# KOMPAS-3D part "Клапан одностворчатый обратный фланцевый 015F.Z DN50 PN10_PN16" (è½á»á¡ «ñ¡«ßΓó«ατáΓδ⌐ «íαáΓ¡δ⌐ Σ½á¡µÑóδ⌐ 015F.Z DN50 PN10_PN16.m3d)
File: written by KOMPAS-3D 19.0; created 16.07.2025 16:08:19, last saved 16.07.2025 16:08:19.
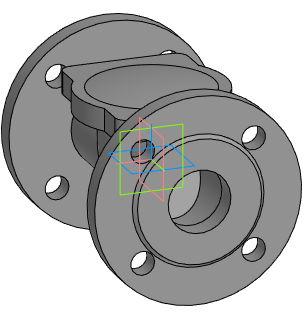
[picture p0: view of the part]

Document properties: Полное имя файла: E:\Dendor Работа Сачек\3D для проектировщиков\5.4 Тип 015F.Z. Клапан одностворчатый обратный фланцевый\stp_Клапан одностворчатый обратный фланцевый 015F.Z PN10_16\Клапан одностворчатый обратный фланцевый 015F.Z DN50 PN10_PN16.m3d

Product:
- Part/product: Клапан одностворчатый обратный фланцевый 015F.Z DN50 PN10_PN16

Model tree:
1. Операция без истории:1
2. Операция без истории:2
